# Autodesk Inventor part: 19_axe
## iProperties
Created: 2002-11
Part Number: 19_axe
Material: Par défaut
Document SubType Name: Modélisation
Designer: FIEVET
Control State: 0
Master: False
Checked Out: False
Shininess: 78.0
Length Units: 11269
Angle Units: 11279
Time Units: 11290
Mass Units: 11283
Length Display Precision: 3
Angle Display Precision: 2
Compacted: True
Density: 0.0
Volumn: 0.0
Area: 0.0
PropertySet Name: Model Information
Author: FIEVET
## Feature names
1. Révolution1 [Revolution]
